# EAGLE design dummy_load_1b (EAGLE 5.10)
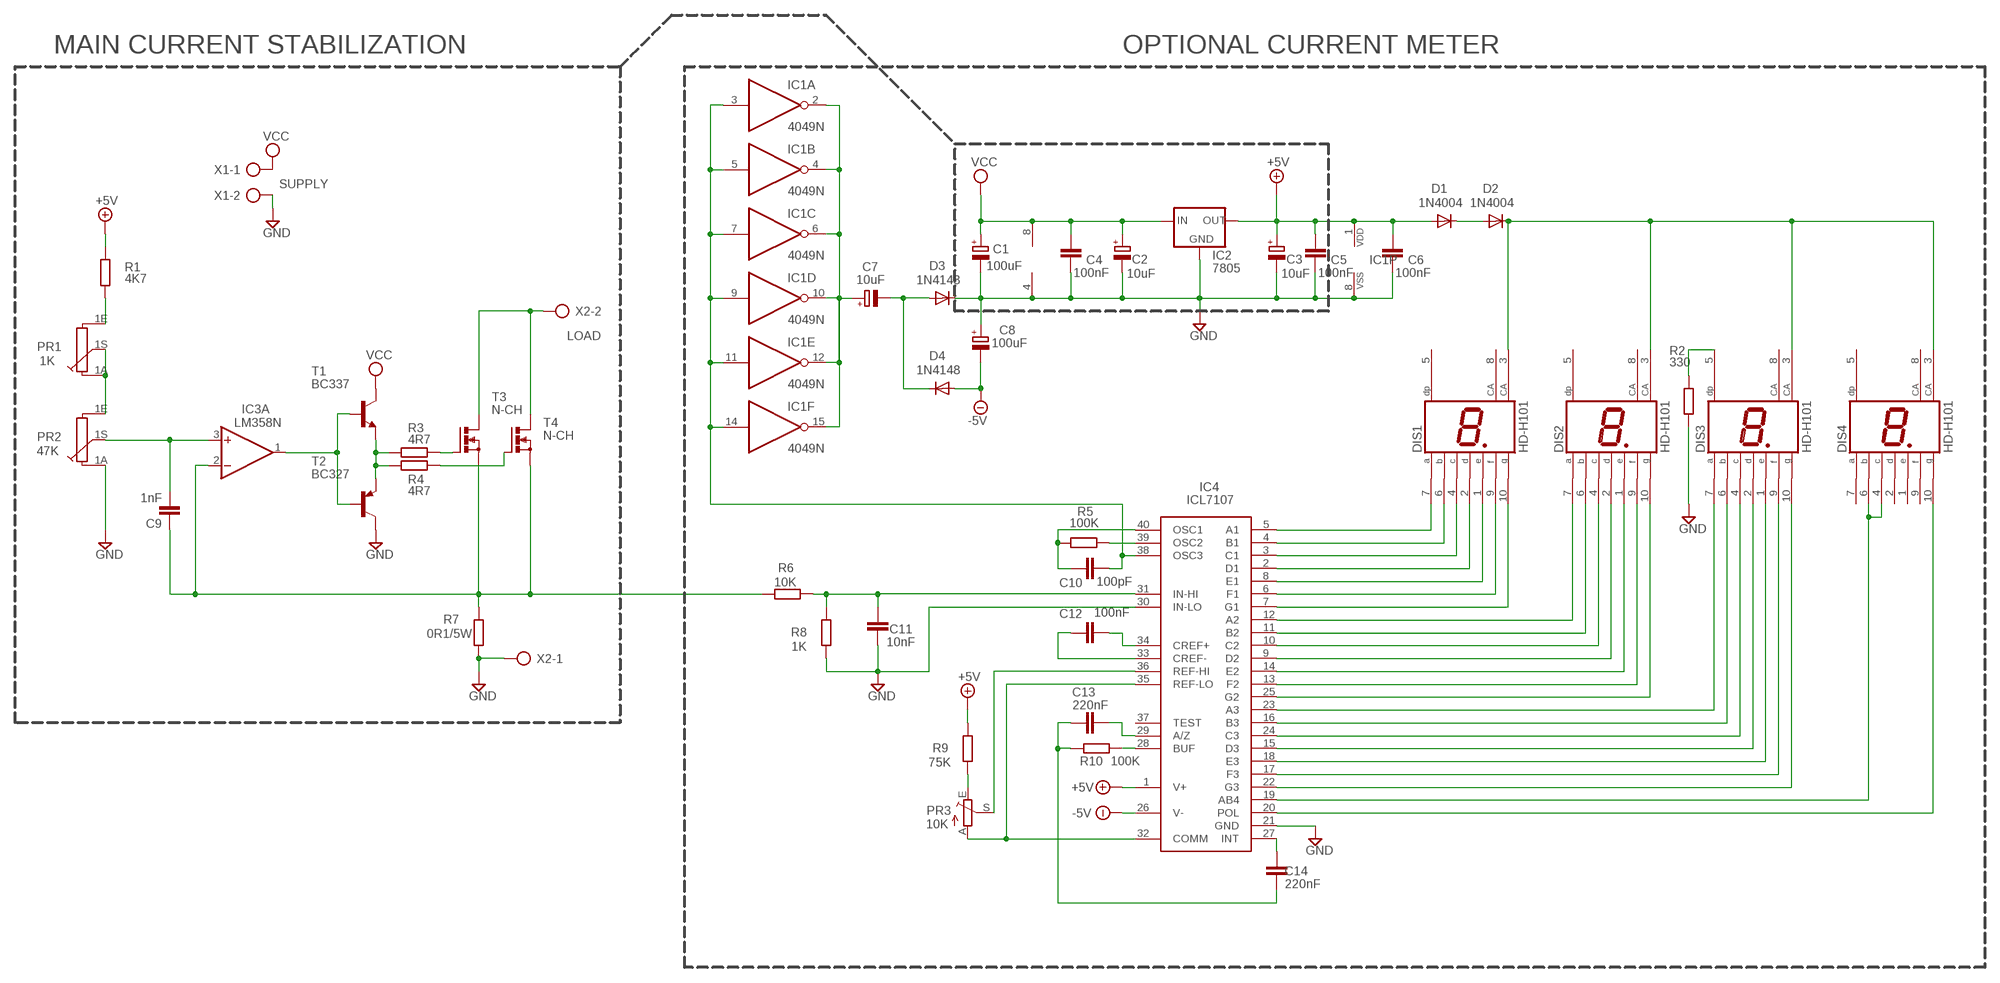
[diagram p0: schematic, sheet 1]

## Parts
C1  100uF  CPOL-EUE2.5-6  [E2,5-6]
C2  10uF  CPOL-EUE2.5-6  [E2,5-6]
C3  10uF  CPOL-EUE2.5-6  [E2,5-6]
C4  100nF  C-EU050-025X075  [C050-025X075]
C5  100nF  C-EU050-025X075  [C050-025X075]
C6  100nF  C-EU050-025X075  [C050-025X075]
C7  10uF  CPOL-EUE2.5-6  [E2,5-6]
C8  100uF  CPOL-EUE2.5-6  [E2,5-6]
C9  1nF  C-EU050-025X075  [C050-025X075]
C10  100pF  C-EU050-025X075  [C050-025X075]
C11  10nF  C-EU050-025X075  [C050-025X075]
C12  100nF  C-EU050-025X075  [C050-025X075]
C13  220nF  C-EU050-025X075  [C050-025X075]
C14  220nF  C-EU050-025X075  [C050-025X075]
D1  1N4004  [DO41-10]
D2  1N4004  [DO41-10]
D3  1N4148  [DO35-10]
D4  1N4148  [DO35-10]
DIS1  HD-H101  [HDSP-M]
DIS2  HD-H101  [HDSP-M]
DIS3  HD-H101  [HDSP-M]
DIS4  HD-H101  [HDSP-M]
IC1  4049N  [DIL16]
IC2  7805  78XXS  [78XXS]
IC3  LM358N  [DIL08]
IC4  ICL7107  ICL7107CPL1  [DIL40]
PR1  1K  PC16S  [PC16S]
PR2  47K  PC16S  [PC16S]
PR3  10K  TRIM_EU-B90P  [SP19L]
R1  4K7  R-EU_0207/7  [0207/7]
R2  330  R-EU_0207/7  [0207/7]
R3  4R7  R-EU_0207/7  [0207/7]
R4  4R7  R-EU_0207/15  [0207/15]
R5  100K  R-EU_0207/7  [0207/7]
R6  10K  R-EU_0207/7  [0207/7]
R7  0R1/5W  R-EU_0922/22  [0922/22]
R8  1K  R-EU_0207/7  [0207/7]
R9  75K  R-EU_0207/7  [0207/7]
R10  100K  R-EU_0207/7  [0207/7]
T1  BC337  BC337-40-NPN-TO92-EBC  [TO92-EBC]
T2  BC327  BC327-40-PNP-TO92-EBC  [TO92-EBC]
T3  N-CH  BUZ11BV  [TO220BV]
T4  N-CH  BUZ11BV  [TO220BV]
X1  SUPPLY  AK500/2  [AK500/2]
X2  LOAD  AK500/2  [AK500/2]

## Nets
+5V: C3.+ C5.2 C6.2 D1.A IC1.1(P:VDD) IC2.OUT IC4.1(V+) R1.2 R9.2
-5V: C8.- D4.A IC4.26(V-)
GND: C1.- C2.- C3.- C4.1 C5.1 C6.1 C8.+ C11.1 D3.C IC1.8(P:VSS) IC2.GND IC3.4(P:V-) IC4.21(GND) IC4.30(IN-LO) PR2.1A R2.2 R7.1 R8.1 T2.C X1.2 X2.1
N$1: D1.C D2.A
N$2: D2.C DIS1.3(CA) DIS2.3(CA) DIS3.3(CA) DIS4.3(CA)
N$3: DIS3.5(DP) R2.1
N$4: DIS1.7(A) IC4.5(A1)
N$5: DIS1.6(B) IC4.4(B1)
N$6: DIS1.4(C) IC4.3(C1)
N$7: DIS1.2(D) IC4.2(D1)
N$8: DIS1.1(E) IC4.8(E1)
N$9: DIS1.9(F) IC4.6(F1)
N$10: DIS1.10(G) IC4.7(G1)
N$11: DIS2.7(A) IC4.12(A2)
N$12: DIS2.6(B) IC4.11(B2)
N$13: DIS2.4(C) IC4.10(C2)
N$14: DIS2.2(D) IC4.9(D2)
N$15: DIS2.1(E) IC4.14(E2)
N$16: DIS2.9(F) IC4.13(F2)
N$17: DIS2.10(G) IC4.25(G2)
N$18: DIS3.7(A) IC4.23(A3)
N$19: DIS3.6(B) IC4.16(B3)
N$20: T3.D T4.D X2.2
N$21: DIS3.2(D) IC4.15(D3)
N$22: DIS3.1(E) IC4.18(E3)
N$23: DIS3.9(F) IC4.17(F3)
N$24: DIS3.10(G) IC4.22(G3)
N$25: DIS4.4(C) DIS4.6(B) IC4.19(AB4)
N$26: IC4.32(COMM) IC4.35(REF-LO) PR3.A
N$27: C10.1 IC4.40(OSC1) R5.1
N$28: IC4.39(OSC2) R5.2
N$29: PR1.1A PR1.1S PR2.1E
N$30: C12.2 IC4.34(CREF+)
N$31: C12.1 IC4.33(CREF-)
N$32: IC4.36(REF-HI) PR3.S
N$33: C11.2 IC4.31(IN-HI) R6.1 R8.2
N$34: PR3.E R9.1
N$35: IC4.28(BUF) R10.2
N$36: C13.2 IC4.29(A/Z)
N$37: C13.1 C14.1 R10.1
N$38: C14.2 IC4.27(INT)
N$39: C7.+ IC1.2(A:O) IC1.4(B:O) IC1.6(C:O) IC1.10(D:O) IC1.12(E:O) IC1.15(F:O)
N$40: C10.2 IC1.3(A:I) IC1.5(B:I) IC1.7(C:I) IC1.9(D:I) IC1.11(E:I) IC1.14(F:I) IC4.38(OSC3)
N$41: C7.- D3.A D4.C
N$42: C9.2 IC3.3(A:+IN) PR2.1S
N$43: IC3.1(A:OUT) T1.B T2.B
N$44: R3.1 R4.1 T1.E T2.E
N$45: R4.2 T4.G
N$46: PR1.1E R1.1
N$47: R3.2 T3.G
N$48: DIS4.10(G) IC4.20(POL)
N$49: DIS3.4(C) IC4.24(C3)
N$52: C9.1 IC3.2(A:-IN) R6.2 R7.2 T3.S T4.S
VCC: C1.+ C2.+ C4.2 IC2.IN IC3.8(P:V+) T1.C X1.1
Unconnected: DIS1.5(DP) DIS1.8(CA) DIS2.5(DP) DIS2.8(CA) DIS3.8(CA) DIS4.1(E) DIS4.2(D) DIS4.5(DP) DIS4.7(A) DIS4.8(CA) DIS4.9(F) IC3.5(B:+IN) IC3.6(B:-IN) IC3.7(B:OUT) IC4.37(TEST)

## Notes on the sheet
- MAIN CURRENT STABILIZATION | OPTIONAL CURRENT METER

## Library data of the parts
C1-C3 C7 C8 = rcl:CPOL-EU: POLARIZED CAPACITOR, European symbol
C4-C6 C9-C14 = rcl:C-EU: CAPACITOR, European symbol
D1 D2 = diode:1N4004: DIODE
D3 D4 = diode:1N4148: DIODE
DIS1-DIS4 = display-hp:HD-H101: LED DISPLAY 1-character 7 segment, decimal point right
IC1 = 40xx:4049: Hex inverting BUFFER
IC2 = v-reg:78XXS: VOLTAGE REGULATOR
IC3 = linear:LM358: OP AMP also LM158; LM258; LM2904 Source: http://cache.national.com/ds/LM/LM158.pdf
IC4 = maxim-3:ICL7107CPL: LED DRIVER
PR1 PR2 = piher:PC16S: POTENTIOMETER single carbon potentiometer, 16 mm, S3ROH
PR3 = pot:TRIM_EU-: POTENTIOMETER
R1-R10 = rcl:R-EU_: RESISTOR, European symbol
T1 = transistor:*-NPN-: NPN Transistror
T2 = transistor:*-PNP-: PNP Transistror
T3 T4 = transistor-power:BUZ11: N-CHANNEL MOS FET
X1 X2 = con-ptr500:AK500/2: CONNECTOR

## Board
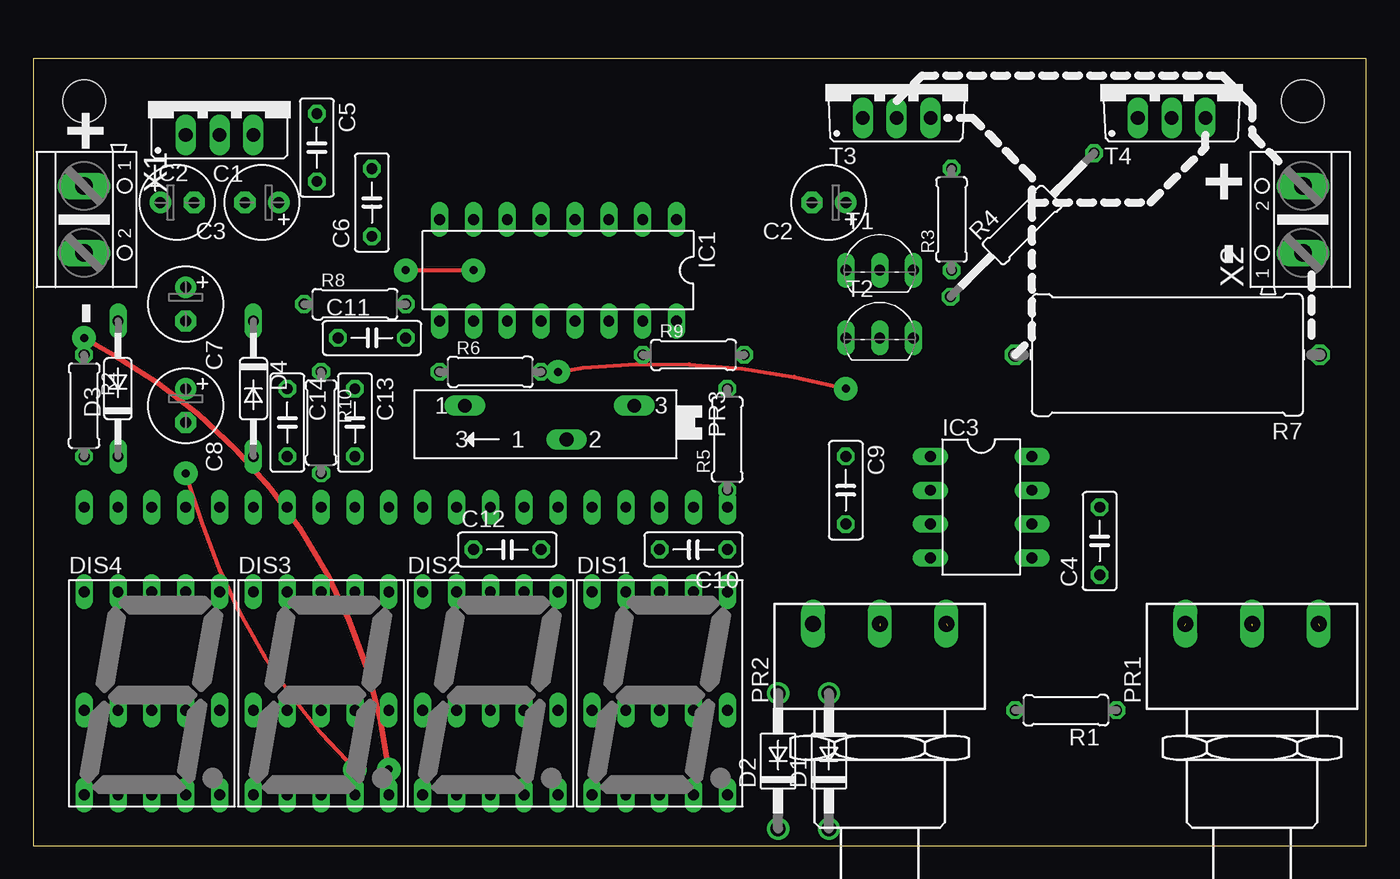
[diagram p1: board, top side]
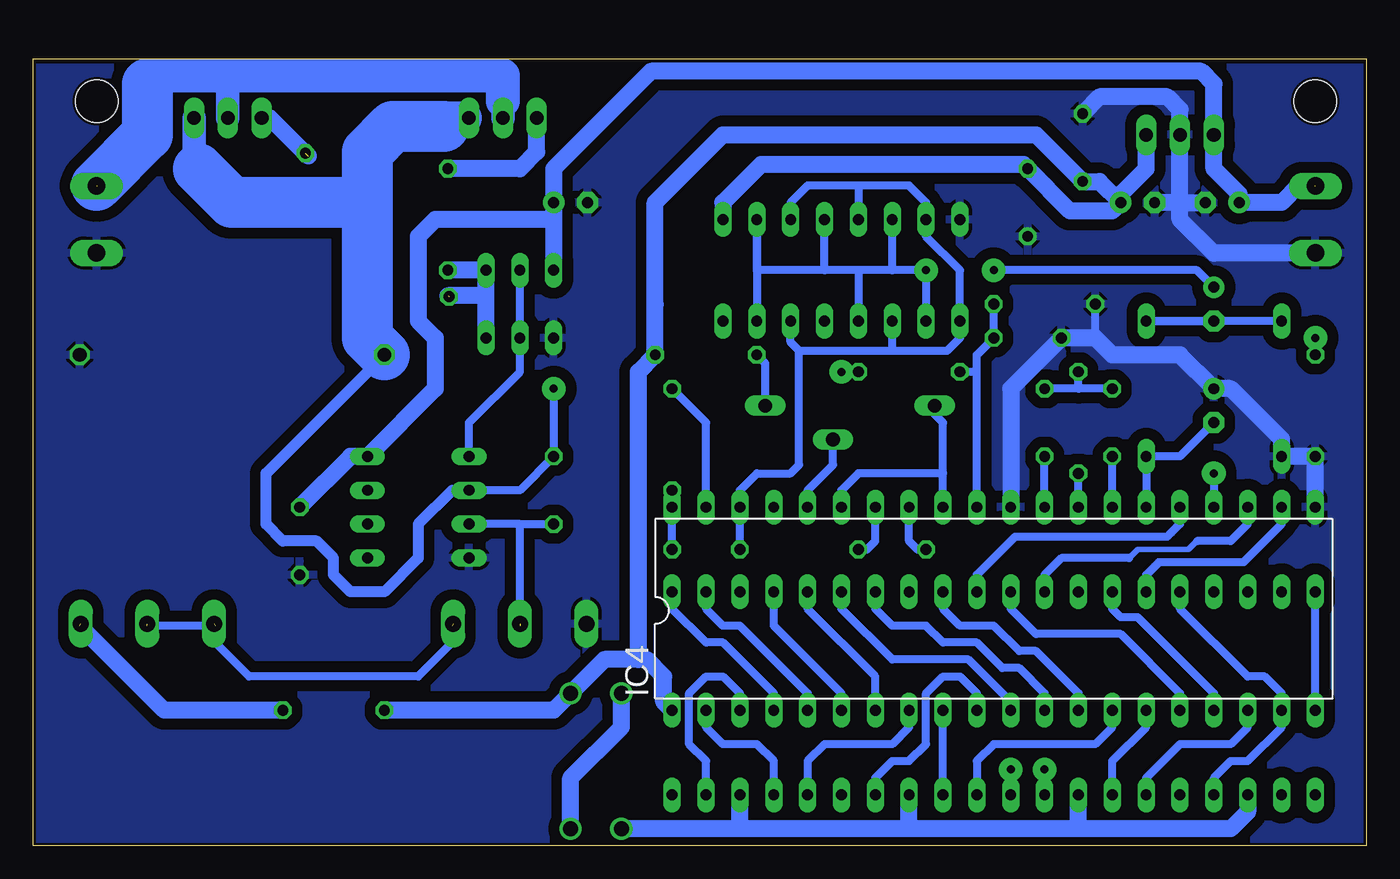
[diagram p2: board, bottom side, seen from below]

Size 100 x 59.05 mm. Coordinates in mm from the lower left corner, seen from the top.
Outline: 0,0 100,0 100,59.05 0,59.05 0,0
Copper layers (1*16): Top 0.035mm / dielectric 1.5mm / Bottom 0.035mm
Design rules "default *": minimum track width 10mil, minimum drill 24mil, track to track 32mil, track to pad 32mil, pad to pad 8mil, via to via 8mil, smd to smd 8mil, copper to edge 8mil, drill to drill 8mil, minimum pad ring 10mil, minimum via ring 8mil, stop-mask expansion 4mil, vias tented up to drill 0mil, thermal gap 10mil
Holes 3.2 mm at 3.81,55.88 95.25,55.88

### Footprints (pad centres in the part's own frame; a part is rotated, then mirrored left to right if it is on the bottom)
E2,5-6 = drill 0.813 pad 1.6 round: + -1.27,0 | drill 0.813 pad 1.6 octagon: - 1.27,0
C050-025X075 = drill 0.813 octagon: 1 -2.54,0; 2 2.54,0
DO41-10 = drill 1.118 round: A 5.08,0; C -5.08,0
DO35-10 = drill 0.813 long: A 5.08,0; C -5.08,0
HDSP-M = drill 0.813 long: 1 -5.08,-7.62; 2 -2.54,-7.62; 3 0,-7.62; 4 2.54,-7.62; 5 5.08,-7.62; 6 5.08,7.62; 7 2.54,7.62; 8 0,7.62; 9 -2.54,7.62; 10 -5.08,7.62
DIL16 = drill 0.813 long: 1 -8.89,-3.81; 2 -6.35,-3.81; 3 -3.81,-3.81; 4 -1.27,-3.81; 5 1.27,-3.81; 6 3.81,-3.81; 7 6.35,-3.81; 8 8.89,-3.81; 9 8.89,3.81; 10 6.35,3.81; 11 3.81,3.81; 12 1.27,3.81; 13 -1.27,3.81; 14 -3.81,3.81; 15 -6.35,3.81; 16 -8.89,3.81
78XXS = drill 1.016 long: GND 0,-2.54; IN -2.54,-2.54; OUT 2.54,-2.54
DIL08 = drill 0.813 long: 1 -3.81,-3.81; 2 -1.27,-3.81; 3 1.27,-3.81; 4 3.81,-3.81; 5 3.81,3.81; 6 1.27,3.81; 7 -1.27,3.81; 8 -3.81,3.81
DIL40 = drill 0.813 long: 1 -24.13,-7.62; 2 -21.59,-7.62; 3 -19.05,-7.62; 4 -16.51,-7.62; 5 -13.97,-7.62; 6 -11.43,-7.62; 7 -8.89,-7.62; 8 -6.35,-7.62; 9 -3.81,-7.62; 10 -1.27,-7.62; 11 1.27,-7.62; 12 3.81,-7.62; 13 6.35,-7.62; 14 8.89,-7.62; 15 11.43,-7.62; 16 13.97,-7.62; 17 16.51,-7.62; 18 19.05,-7.62; 19 21.59,-7.62; 20 24.13,-7.62; 21 24.13,7.62; 22 21.59,7.62; 23 19.05,7.62; 24 16.51,7.62; 25 13.97,7.62; 26 11.43,7.62; 27 8.89,7.62; 28 6.35,7.62; 29 3.81,7.62; 30 1.27,7.62; 31 -1.27,7.62; 32 -3.81,7.62; 33 -6.35,7.62; 34 -8.89,7.62; 35 -11.43,7.62; 36 -13.97,7.62; 37 -16.51,7.62; 38 -19.05,7.62; 39 -21.59,7.62; 40 -24.13,7.62
PC16S = drill 1.2 long: 1A -5,6.5; 1E 5,6.5; 1S 0,6.5
SP19L = drill 1.016 long: A 5.715,-1.27; E -6.985,-1.27; S -1.905,1.27
0207/7 = drill 0.813 octagon: 1 -3.81,0; 2 3.81,0
0207/15 = drill 0.813 octagon: 1 -7.62,0; 2 7.62,0
0922/22 = drill 1.016 octagon: 1 -11.43,0; 2 11.43,0
TO92-EBC = drill 0.813 long: B 0,-1.27; C -2.54,-1.27; E 2.54,-1.27
TO220BV = drill 1.016 long: D 0,-2.54; G -2.54,-2.54; S 2.54,-2.54
AK500/2 = drill 1.321 long: 1 -2.515,0; 2 2.515,0

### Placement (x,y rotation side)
C1  10.79,48.26 0 top
C2  59.69,48.26 180 top
C3  17.14,48.26 180 top
C4  80.01,22.86 90 top
C5  21.27,52.39 270 top
C6  25.4,48.26 90 top
C7  11.43,40.64 270 top
C8  11.43,33.02 270 top
C9  60.96,26.67 270 top
C10  49.53,22.23 180 top
C11  25.4,38.1 0 top
C12  35.56,22.23 0 top
C13  24.13,31.75 270 top
C14  19.05,31.75 270 top
D1  59.69,6.35 90 top
D2  55.88,6.35 90 top
D3  6.35,34.29 90 top
D4  16.51,34.29 270 top
DIS1  46.99,11.43 0 top
DIS2  34.29,11.43 0 top
DIS3  21.59,11.43 0 top
DIS4  8.89,11.43 0 top
IC1  39.37,43.18 180 top
IC2  13.97,55.88 0 top
IC3  71.12,25.4 270 top
IC4  27.94,17.78 0 bottom
PR1  91.44,10.16 0 top
PR2  63.5,10.16 0 top
PR3  38.1,31.75 180 top
R1  77.47,10.16 180 top
R2  3.81,33.02 270 top
R3  68.9,46.99 90 top
R4  74.2,46.58 45 top
R5  52.07,30.48 90 top
R6  34.29,35.56 0 top
R7  85.09,36.83 180 top
R8  24.13,40.64 0 top
R9  49.53,36.83 0 top
R10  21.59,31.75 270 top
T1  63.5,44.45 0 top
T2  63.5,39.37 0 top
T3  64.77,57.15 0 top
T4  85.41,57.15 0 top
X1  3.81,46.99 270 top
X2  95.25,46.99 90 top

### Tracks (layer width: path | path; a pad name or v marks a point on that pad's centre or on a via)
+5V
  Bottom 1.27: 54.61,13.97 53.98,13.97 52.7,12.7 52.7,10.79 IC4.1 | 54.61,13.97 57.15,13.97 D1.A 60.96,10.16 R1.2 | R9.2 54.61,35.56 54.61,13.97 | R9.2 53.34,40.64 | C3.+ 18.41,48.9 16.51,50.8 IC2.OUT | C3.+ 20,49.85 C5.2 24.77,53.34 48.26,53.34 53.34,48.26 R9.2 | C3.+ 19.05,47.62 22.23,47.62 C6.2 25.72,51.12 45.4,51.12 48.26,48.26 IC1.1
-5V
  Bottom 0.61: IC4.26 D4.A 13.97,29.21 C8.-
GND
  Bottom 0.61: 20.32,38.1 R8.1
  Bottom 1.27: IC4.30 26.67,34.29 C11.1 20.32,38.1 19.05,36.83 13.97,36.83 C8.+ 10.16,34.29 6.35,30.48 D3.C R2.2 IC4.21 | 13.97,48.26 C3.- | 13.97,48.26 C1.- | C5.1 20,56.2 14.92,56.2 13.97,55.24 IC2.GND 13.97,48.26 | 13.97,48.26 13.97,46.99 11.43,44.45 3.81,44.45
  pour Bottom: 0,58.42 0,0 100.33,0 100.33,58.42
N$1
  Bottom 1.27: D2.A 55.88,8.89 59.69,5.08 D1.C
N$2
  Bottom 1.27: DIS4.3 8.89,2.54 10.16,1.27 21.59,1.27 | 21.59,1.27 DIS3.3 | 21.59,1.27 34.29,1.27 | 34.29,1.27 DIS2.3 | 34.29,1.27 46.99,1.27 | 46.99,1.27 DIS1.3 | 46.99,1.27 D2.C
N$3  (via drill 0.6 pad 1.78)
  Top 0.406: v3.81,38.1 6.03,36.83 arc-53 v26.67,5.71
  Bottom 0.61: v3.81,38.1 R2.1 | 26.67,5.08 DIS3.5 v26.67,5.71
N$4
  Bottom 0.61: IC4.5 41.91,11.43 46.99,16.51 48.26,16.51 49.53,17.78 DIS1.7
N$5
  Bottom 0.61: IC4.4 44.45,11.43 48.26,15.24 49.53,15.24 52.07,17.78 DIS1.6
N$6
  Bottom 0.61: IC4.3 46.99,11.43 48.26,12.7 49.53,12.7 50.8,11.43 50.8,7.62 49.53,6.35 DIS1.4
N$7
  Bottom 0.61: IC4.2 49.53,8.89 48.26,7.62 45.72,7.62 44.45,6.35 DIS1.2
N$8
  Bottom 0.61: IC4.8 34.29,8.89 35.56,7.62 40.64,7.62 41.91,6.35 DIS1.1
N$9
  Bottom 0.61: IC4.6 39.37,11.43 44.45,16.51 DIS1.9
N$10
  Bottom 0.61: IC4.7 36.83,12.7 41.91,17.78 DIS1.10
N$11
  Bottom 0.61: IC4.12 24.13,11.43 26.04,13.34 27.3,13.34 29.21,15.24 31.75,15.24 33.02,16.51 35.56,16.51 36.83,17.78 DIS2.7
N$12
  Bottom 0.61: IC4.11 26.67,10.79 29.84,13.97 35.56,13.97 39.37,17.78 DIS2.6
N$13
  Bottom 0.61: IC4.10 29.21,11.43 30.48,12.7 31.75,12.7 33.02,11.43 33.02,7.62 34.29,6.35 35.56,6.35 36.83,5.08 DIS2.4
N$14
  Bottom 0.61: DIS2.2 IC4.9
N$15
  Bottom 0.61: IC4.14 19.05,8.89 20.32,7.62 27.94,7.62 29.21,6.35 DIS2.1
N$16
  Bottom 0.61: IC4.13 21.59,11.43 24.77,14.61 26.04,14.61 27.94,16.51 30.48,16.51 31.75,17.78 DIS2.9
N$17
  Bottom 0.61: IC4.25 13.97,24.13 14.61,23.5 14.92,23.18 23.5,23.18 26.35,23.18 29.21,20.32 DIS2.10
N$18
  Bottom 0.406: 12.7,22.86 13.34,22.23 17.14,22.23 17.78,21.59
  Bottom 0.61: IC4.23 8.89,24.13 10.16,22.86 12.7,22.86 | 17.78,21.59 22.86,21.59 24.13,20.32 DIS3.7
N$19
  Bottom 0.61: IC4.16 13.97,11.43 18.41,15.88 24.77,15.88 26.67,17.78 DIS3.6
N$20  (1 unrouted)
  Bottom 1.778: T3.D 64.77,55.88 | 85.41,57.78 T4.D
  Bottom 2.54: 91.44,57.15 90.81,57.78 85.41,57.78 64.77,57.78 64.77,55.88
  Bottom 3.81: 91.44,57.15 91.44,53.34 95.25,49.53
N$21
  Bottom 0.61: IC4.15 16.51,8.89 19.05,6.35 DIS3.2
N$22
  Bottom 0.61: IC4.18 8.89,8.89 10.16,7.62 13.97,7.62 16.51,5.08 DIS3.1
N$23
  Bottom 0.61: IC4.17 11.43,11.43 17.14,17.14 18.41,17.14 19.05,17.78 DIS3.9
N$24
  Bottom 0.61: IC4.22 6.35,24.13 8.57,21.91 9.21,21.27 15.56,21.27 15.88,20.95 16.51,20.32 DIS3.10
N$25
  Bottom 0.61: DIS4.6 13.97,17.78 8.89,12.7 7.62,12.7 6.35,11.43 IC4.19 6.35,8.89 8.89,6.35 10.16,6.35 11.43,5.08 DIS4.4
N$26
  Bottom 0.61: IC4.35 39.37,26.67 38.1,27.94 31.75,27.94 | IC4.32 31.75,27.94 | 31.75,27.94 31.75,31.75 32.38,32.38 PR3.A
N$27
  Bottom 0.61: R5.1 IC4.40 C10.1
N$28
  Bottom 0.61: R5.2 49.53,31.75 IC4.39
N$29  (3 unrouted)
  Bottom 0.61: 68.58,16.51 68.58,15.24 71.12,12.7 83.82,12.7 86.36,15.24 86.36,16.51 91.44,16.51
N$30
  Bottom 0.61: IC4.34 36.83,22.86 37.47,22.23 C12.2
N$31
  Bottom 0.61: IC4.33 34.29,22.86 33.66,22.23 C12.1
N$32
  Bottom 0.61: IC4.36 41.91,26.67 40.01,28.57 PR3.S
N$33
  Bottom 0.61: IC4.31 29.21,35.56 | 29.21,35.56 29.21,36.83 C11.2 R8.2 | 29.21,35.56 R6.1
N$34
  Bottom 0.61: R9.1 45.09,36.2 PR3.E
N$35
  Bottom 0.61: IC4.28 R10.2
N$36
  Bottom 0.61: IC4.29 C13.2
N$37
  Bottom 0.61: C14.1 21.59,34.29 | 21.59,34.29 R10.1 | 21.59,34.29 C13.1
N$38
  Bottom 0.61: IC4.27 C14.2
N$39  (via drill 0.6 pad 1.78)
  Top 0.305: v27.94,43.18 v33.02,43.18
  Bottom 0.61: IC1.10 v33.02,43.18 35.56,43.18 | 35.56,43.18 IC1.6 | 35.56,43.18 38.1,43.18 | 38.1,43.18 IC1.12 | 38.1,43.18 40.64,43.18 | 40.64,43.18 IC1.4 | 40.64,43.18 45.72,43.18 IC1.2 IC1.15 | C7.+ 12.7,43.18 v27.94,43.18
N$40
  Bottom 0.61: 38.1,49.53 34.29,49.53 33.02,48.26 IC1.7 33.02,45.72 30.48,43.18 IC1.9 30.48,38.1 31.43,37.15 35.56,37.15 | 38.1,49.53 IC1.5 | 38.1,49.53 41.91,49.53 43.18,48.26 IC1.3 | IC1.14 43.18,37.78 42.55,37.15 | 42.55,37.15 35.56,37.15 | 35.56,37.15 IC1.11 | C10.2 IC4.38 46.99,26.67 45.72,27.94 43.18,27.94 42.55,28.57 42.55,37.15
N$41
  Bottom 0.61: C7.- D4.C D3.A
N$42  (1 unrouted)
  Bottom 0.61: 63.5,16.51 63.5,24.13 | 63.5,24.13 IC3.3 | 63.5,24.13 C9.2
N$43
  Bottom 0.61: T1.B T2.B 63.5,35.56 67.31,31.75 IC3.1
N$44  (1 unrouted)
  Bottom 1.27: T2.E 66.04,40.64 66.04,41.27 | 66.04,41.27 T1.E R3.1 | 66.04,41.27 68.9,41.27
N$45  (1 unrouted)
  Bottom 1.27: T4.G 82.23,54.61 79.38,51.75
N$46  (1 unrouted)
  Bottom 1.27: R1.1 90.17,10.16 96.52,16.51
N$47
  Bottom 1.27: R3.2 63.5,50.8 62.23,52.07 T3.G
N$48
  Bottom 0.61: IC4.20 DIS4.10
N$49  (via drill 0.6 pad 1.78)
  Top 0.305: v11.43,27.94 12.7,24.13 arc27 v24.13,5.71
  Bottom 0.61: v11.43,27.94 IC4.24 | DIS3.4 v24.13,5.71
N$52  (via drill 0.6 pad 1.78)
  Top 0.305: v39.37,35.56 41.27,35.88 arc-21 v60.96,34.29
  Bottom 0.61: v60.96,34.29 C9.1 63.5,26.67 IC3.2 | R6.2 v39.37,35.56
  Bottom 0.813: R7.2 82.55,27.94 82.55,24.13 81.28,22.86 78.74,22.86 77.47,21.59 77.47,20.32 76.2,19.05 73.66,19.05 71.12,21.59 71.12,24.13 68.58,26.67 IC3.2
  Bottom 1.778: 67.63,54.61 T3.S | 87.63,50.8 87.95,51.12 T4.S
  Bottom 2.54: 69.22,53.98 69.22,54.61 67.63,54.61
  Bottom 3.81: 74.93,48.26 74.93,52.07 73.03,53.98 69.22,53.98 | R7.2 74.93,38.1 74.93,48.26 | 74.93,48.26 85.09,48.26 87.63,50.8
VCC  (1 unrouted)
  Bottom 1.27: 3.81,49.53 5.08,49.53 6.35,48.26 C1.+ 9.53,48.9 11.43,50.8 IC2.IN 11.43,57.15 12.38,58.1 53.66,58.1 60.96,50.8 C2.+ 60.96,46.99 | 60.96,46.99 T1.C | 60.96,46.99 69.85,46.99 71.12,45.72 71.12,39.37 69.85,38.1 69.85,34.29 IC3.8 76.2,29.21 C4.2

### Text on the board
tPlace: + | + | - | -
